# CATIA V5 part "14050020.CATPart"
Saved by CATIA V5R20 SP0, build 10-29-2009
Part number: 14050020
Definition: NONE
Nomenclature: 14050020
Source: Unknown
Description: 14050020
Bounding box of the stored display mesh (mm): x -10 to 40, y -39 to 29.1, z -29.1 to 29.1
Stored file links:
  C:\Users\Utente\Desktop\IO LAVORO\3D X SITO CF\X SITO\PLASTICA\RF2\14050020.CATPart
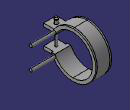
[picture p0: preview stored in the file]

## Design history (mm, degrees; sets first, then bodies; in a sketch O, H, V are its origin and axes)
Body1 "14050020" (main body)
  Solid1: solid without history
